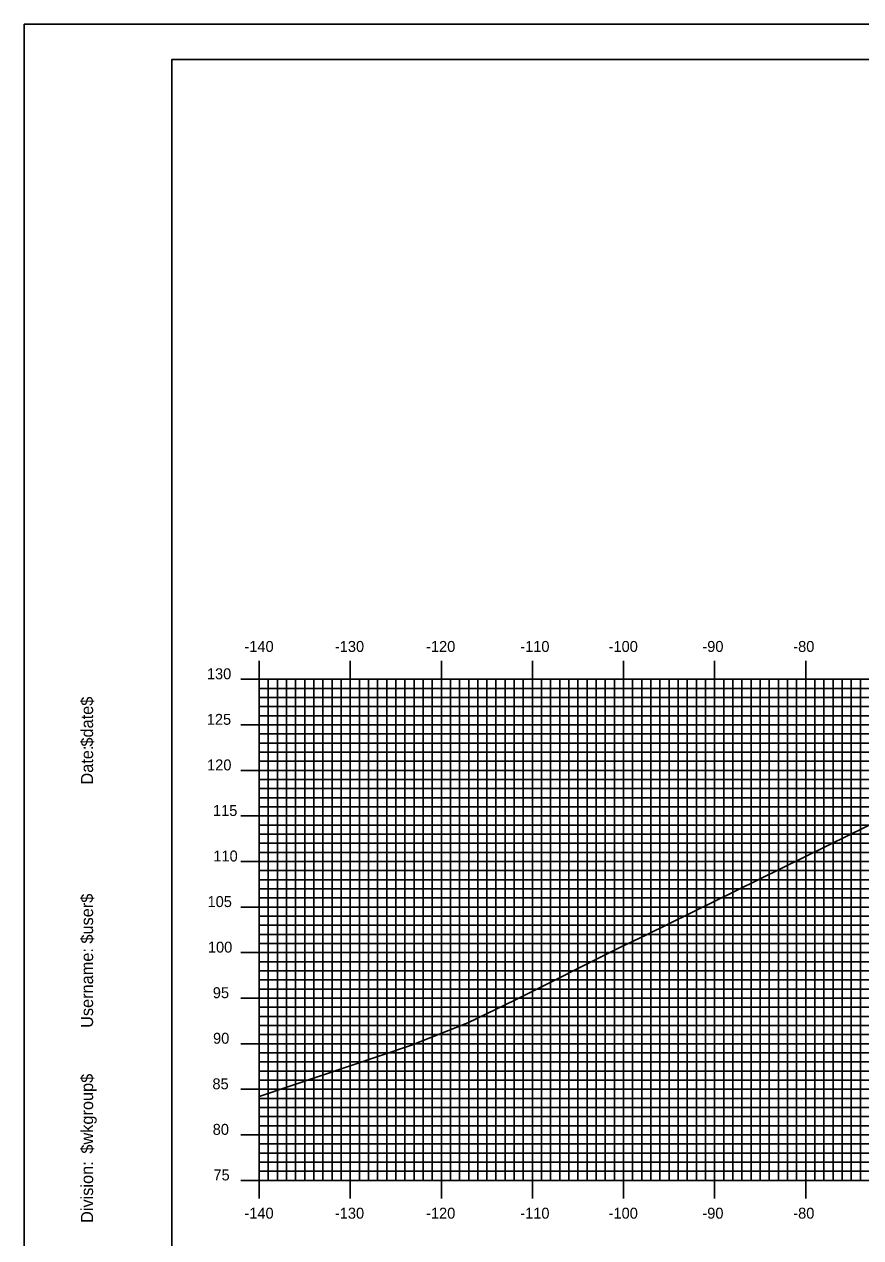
# Model space of a CAD drawing. Extents: x 1684012 to 1684355, y 461260 to 461480.
# Drawn here: x 1684011.9 to 1684103.7, y 461346.8 to 461480 of the extents above; entities that cross this region are included whole.
import ezdxf

# ---------------------------------------------------------------- set-up
doc = ezdxf.new("R2010")
doc.units = 0
for name, color, linetype in [('BORDER', 7, 'Continuous'), ('H_V ANNOTATION', 7, 'Continuous'), ('MAJOR', 7, 'Continuous'), ('MINOR', 7, 'Continuous'), ('PLOT BOUNDARY', 7, 'Continuous'), ('S_Roadway_Centerline', 7, 'Continuous')]:
    doc.layers.add(name, color=color, linetype=linetype)

msp = doc.modelspace()

# ---------------------------------------------------------------- linework, layer by layer
at = {"layer": 'BORDER'}
msp.add_lwpolyline([(1684028.09, 461266.07), (1684348.09, 461266.07), (1684348.09, 461476.07), (1684028.09, 461476.07)], close=True, dxfattribs=at)
at = {"layer": 'MAJOR'}
for p, q in [((1684037.69, 461410.08), (1684037.69, 461408.07)), ((1684047.69, 461410.08), (1684047.69, 461408.07)), ((1684057.69, 461410.08), (1684057.69, 461408.07)), ((1684067.69, 461410.08), (1684067.69, 461408.07)), ((1684077.69, 461410.08), (1684077.69, 461408.07)), ((1684087.69, 461410.08), (1684087.69, 461408.07)), ((1684097.69, 461410.08), (1684097.69, 461408.07)), ((1684035.69, 461408.07), (1684037.69, 461408.07)), ((1684037.69, 461408.07), (1684317.69, 461408.07)), ((1684037.69, 461353.07), (1684037.69, 461408.07)), ((1684037.69, 461353.07), (1684037.69, 461408.07)), ((1684037.69, 461408.07), (1684317.69, 461408.07)), ((1684047.69, 461353.07), (1684047.69, 461408.07)), ((1684057.69, 461353.07), (1684057.69, 461408.07)), ((1684067.69, 461353.07), (1684067.69, 461408.07)), ((1684077.69, 461353.07), (1684077.69, 461408.07)), ((1684087.69, 461353.07), (1684087.69, 461408.07)), ((1684097.69, 461353.07), (1684097.69, 461408.07)), ((1684035.69, 461403.07), (1684037.69, 461403.07)), ((1684037.69, 461403.07), (1684317.69, 461403.07)), ((1684035.69, 461398.07), (1684037.69, 461398.07)), ((1684037.69, 461398.07), (1684317.69, 461398.07)), ((1684035.69, 461393.07), (1684037.69, 461393.07)), ((1684037.69, 461393.07), (1684317.69, 461393.07)), ((1684035.69, 461388.07), (1684037.69, 461388.07)), ((1684037.69, 461388.07), (1684317.69, 461388.07)), ((1684035.69, 461383.07), (1684037.69, 461383.07)), ((1684037.69, 461383.07), (1684317.69, 461383.07)), ((1684035.69, 461378.07), (1684037.69, 461378.07)), ((1684037.69, 461378.07), (1684317.69, 461378.07)), ((1684035.69, 461373.07), (1684037.69, 461373.07)), ((1684037.69, 461373.07), (1684317.69, 461373.07)), ((1684035.69, 461368.07), (1684037.69, 461368.07)), ((1684037.69, 461368.07), (1684317.69, 461368.07)), ((1684035.69, 461363.07), (1684037.69, 461363.07)), ((1684037.69, 461363.07), (1684317.69, 461363.07)), ((1684035.69, 461358.07), (1684037.69, 461358.07)), ((1684037.69, 461358.07), (1684317.69, 461358.07)), ((1684035.69, 461353.07), (1684037.69, 461353.07)), ((1684037.69, 461353.07), (1684317.69, 461353.07)), ((1684037.69, 461353.07), (1684317.69, 461353.07)), ((1684037.69, 461351.07), (1684037.69, 461353.07)), ((1684047.69, 461351.07), (1684047.69, 461353.07)), ((1684057.69, 461351.07), (1684057.69, 461353.07)), ((1684067.69, 461351.07), (1684067.69, 461353.07)), ((1684077.69, 461351.07), (1684077.69, 461353.07)), ((1684087.69, 461351.07), (1684087.69, 461353.07)), ((1684097.69, 461351.07), (1684097.69, 461353.07))]:
    msp.add_line(p, q, dxfattribs=at)
at = {"layer": 'MINOR'}
for p, q in [((1684038.69, 461353.07), (1684038.69, 461408.07)), ((1684039.69, 461353.07), (1684039.69, 461408.07)), ((1684040.69, 461353.07), (1684040.69, 461408.07)), ((1684041.69, 461353.07), (1684041.69, 461408.07)), ((1684042.69, 461353.07), (1684042.69, 461408.07)), ((1684043.69, 461353.07), (1684043.69, 461408.07)), ((1684044.69, 461353.07), (1684044.69, 461408.07)), ((1684045.69, 461353.07), (1684045.69, 461408.07)), ((1684046.69, 461353.07), (1684046.69, 461408.07)), ((1684048.69, 461353.07), (1684048.69, 461408.07)), ((1684049.69, 461353.07), (1684049.69, 461408.07)), ((1684050.69, 461353.07), (1684050.69, 461408.07)), ((1684051.69, 461353.07), (1684051.69, 461408.07)), ((1684052.69, 461353.07), (1684052.69, 461408.07)), ((1684053.69, 461353.07), (1684053.69, 461408.07)), ((1684054.69, 461353.07), (1684054.69, 461408.07)), ((1684055.69, 461353.07), (1684055.69, 461408.07)), ((1684056.69, 461353.07), (1684056.69, 461408.07)), ((1684058.69, 461353.07), (1684058.69, 461408.07)), ((1684059.69, 461353.07), (1684059.69, 461408.07)), ((1684060.69, 461353.07), (1684060.69, 461408.07)), ((1684061.69, 461353.07), (1684061.69, 461408.07)), ((1684062.69, 461353.07), (1684062.69, 461408.07)), ((1684063.69, 461353.07), (1684063.69, 461408.07)), ((1684064.69, 461353.07), (1684064.69, 461408.07)), ((1684065.69, 461353.07), (1684065.69, 461408.07)), ((1684066.69, 461353.07), (1684066.69, 461408.07)), ((1684068.69, 461353.07), (1684068.69, 461408.07)), ((1684069.69, 461353.07), (1684069.69, 461408.07)), ((1684070.69, 461353.07), (1684070.69, 461408.07)), ((1684071.69, 461353.07), (1684071.69, 461408.07)), ((1684072.69, 461353.07), (1684072.69, 461408.07)), ((1684073.69, 461353.07), (1684073.69, 461408.07)), ((1684074.69, 461353.07), (1684074.69, 461408.07)), ((1684075.69, 461353.07), (1684075.69, 461408.07)), ((1684076.69, 461353.07), (1684076.69, 461408.07)), ((1684078.69, 461353.07), (1684078.69, 461408.07)), ((1684079.69, 461353.07), (1684079.69, 461408.07)), ((1684080.69, 461353.07), (1684080.69, 461408.07)), ((1684081.69, 461353.07), (1684081.69, 461408.07)), ((1684082.69, 461353.07), (1684082.69, 461408.07)), ((1684083.69, 461353.07), (1684083.69, 461408.07)), ((1684084.69, 461353.07), (1684084.69, 461408.07)), ((1684085.69, 461353.07), (1684085.69, 461408.07)), ((1684086.69, 461353.07), (1684086.69, 461408.07)), ((1684088.69, 461353.07), (1684088.69, 461408.07)), ((1684089.69, 461353.07), (1684089.69, 461408.07)), ((1684090.69, 461353.07), (1684090.69, 461408.07)), ((1684091.69, 461353.07), (1684091.69, 461408.07)), ((1684092.69, 461353.07), (1684092.69, 461408.07)), ((1684093.69, 461353.07), (1684093.69, 461408.07)), ((1684094.69, 461353.07), (1684094.69, 461408.07)), ((1684095.69, 461353.07), (1684095.69, 461408.07)), ((1684096.69, 461353.07), (1684096.69, 461408.07)), ((1684098.69, 461353.07), (1684098.69, 461408.07)), ((1684099.69, 461353.07), (1684099.69, 461408.07)), ((1684100.69, 461353.07), (1684100.69, 461408.07)), ((1684101.69, 461353.07), (1684101.69, 461408.07)), ((1684102.69, 461353.07), (1684102.69, 461408.07)), ((1684103.69, 461353.07), (1684103.69, 461408.07)), ((1684037.69, 461407.07), (1684317.69, 461407.07)), ((1684037.69, 461407.07), (1684039.69, 461407.07)), ((1684037.69, 461406.07), (1684317.69, 461406.07)), ((1684037.69, 461406.07), (1684039.69, 461406.07)), ((1684037.69, 461405.07), (1684317.69, 461405.07)), ((1684037.69, 461405.07), (1684039.69, 461405.07)), ((1684037.69, 461404.07), (1684317.69, 461404.07)), ((1684037.69, 461404.07), (1684039.69, 461404.07)), ((1684037.69, 461402.07), (1684317.69, 461402.07)), ((1684037.69, 461402.07), (1684039.69, 461402.07)), ((1684037.69, 461401.07), (1684317.69, 461401.07)), ((1684037.69, 461401.07), (1684039.69, 461401.07)), ((1684037.69, 461400.07), (1684317.69, 461400.07)), ((1684037.69, 461400.07), (1684039.69, 461400.07)), ((1684037.69, 461399.07), (1684317.69, 461399.07)), ((1684037.69, 461399.07), (1684039.69, 461399.07)), ((1684037.69, 461397.07), (1684317.69, 461397.07)), ((1684037.69, 461397.07), (1684039.69, 461397.07)), ((1684037.69, 461396.07), (1684317.69, 461396.07)), ((1684037.69, 461396.07), (1684039.69, 461396.07)), ((1684037.69, 461395.07), (1684317.69, 461395.07)), ((1684037.69, 461395.07), (1684039.69, 461395.07)), ((1684037.69, 461394.07), (1684317.69, 461394.07)), ((1684037.69, 461394.07), (1684039.69, 461394.07)), ((1684037.69, 461392.07), (1684317.69, 461392.07)), ((1684037.69, 461392.07), (1684039.69, 461392.07)), ((1684037.69, 461391.07), (1684317.69, 461391.07)), ((1684037.69, 461391.07), (1684039.69, 461391.07)), ((1684037.69, 461390.07), (1684317.69, 461390.07)), ((1684037.69, 461390.07), (1684039.69, 461390.07)), ((1684037.69, 461389.07), (1684317.69, 461389.07)), ((1684037.69, 461389.07), (1684039.69, 461389.07)), ((1684037.69, 461387.07), (1684317.69, 461387.07)), ((1684037.69, 461387.07), (1684039.69, 461387.07)), ((1684037.69, 461386.07), (1684317.69, 461386.07)), ((1684037.69, 461386.07), (1684039.69, 461386.07)), ((1684037.69, 461385.07), (1684317.69, 461385.07)), ((1684037.69, 461385.07), (1684039.69, 461385.07)), ((1684037.69, 461384.07), (1684317.69, 461384.07)), ((1684037.69, 461384.07), (1684039.69, 461384.07)), ((1684037.69, 461382.07), (1684317.69, 461382.07)), ((1684037.69, 461382.07), (1684039.69, 461382.07)), ((1684037.69, 461381.07), (1684317.69, 461381.07)), ((1684037.69, 461381.07), (1684039.69, 461381.07)), ((1684037.69, 461380.07), (1684317.69, 461380.07)), ((1684037.69, 461380.07), (1684039.69, 461380.07)), ((1684037.69, 461379.07), (1684317.69, 461379.07)), ((1684037.69, 461379.07), (1684039.69, 461379.07)), ((1684037.69, 461377.07), (1684317.69, 461377.07)), ((1684037.69, 461377.07), (1684039.69, 461377.07)), ((1684037.69, 461376.07), (1684317.69, 461376.07)), ((1684037.69, 461376.07), (1684039.69, 461376.07)), ((1684037.69, 461375.07), (1684317.69, 461375.07)), ((1684037.69, 461375.07), (1684039.69, 461375.07)), ((1684037.69, 461374.07), (1684317.69, 461374.07)), ((1684037.69, 461374.07), (1684039.69, 461374.07)), ((1684037.69, 461372.07), (1684317.69, 461372.07)), ((1684037.69, 461372.07), (1684039.69, 461372.07)), ((1684037.69, 461371.07), (1684317.69, 461371.07)), ((1684037.69, 461371.07), (1684039.69, 461371.07)), ((1684037.69, 461370.07), (1684317.69, 461370.07)), ((1684037.69, 461370.07), (1684039.69, 461370.07)), ((1684037.69, 461369.07), (1684317.69, 461369.07)), ((1684037.69, 461369.07), (1684039.69, 461369.07)), ((1684037.69, 461367.07), (1684317.69, 461367.07)), ((1684037.69, 461367.07), (1684039.69, 461367.07)), ((1684037.69, 461366.07), (1684317.69, 461366.07)), ((1684037.69, 461366.07), (1684039.69, 461366.07)), ((1684037.69, 461365.07), (1684317.69, 461365.07)), ((1684037.69, 461365.07), (1684039.69, 461365.07)), ((1684037.69, 461364.07), (1684317.69, 461364.07)), ((1684037.69, 461364.07), (1684039.69, 461364.07)), ((1684037.69, 461362.07), (1684317.69, 461362.07)), ((1684037.69, 461362.07), (1684039.69, 461362.07)), ((1684037.69, 461361.07), (1684317.69, 461361.07)), ((1684037.69, 461361.07), (1684039.69, 461361.07)), ((1684037.69, 461360.07), (1684317.69, 461360.07)), ((1684037.69, 461360.07), (1684039.69, 461360.07)), ((1684037.69, 461359.07), (1684317.69, 461359.07)), ((1684037.69, 461359.07), (1684039.69, 461359.07)), ((1684037.69, 461357.07), (1684317.69, 461357.07)), ((1684037.69, 461357.07), (1684039.69, 461357.07)), ((1684037.69, 461356.07), (1684317.69, 461356.07)), ((1684037.69, 461356.07), (1684039.69, 461356.07)), ((1684037.69, 461355.07), (1684317.69, 461355.07)), ((1684037.69, 461355.07), (1684039.69, 461355.07)), ((1684037.69, 461354.07), (1684317.69, 461354.07)), ((1684037.69, 461354.07), (1684039.69, 461354.07))]:
    msp.add_line(p, q, dxfattribs=at)
at = {"layer": 'PLOT BOUNDARY'}
msp.add_lwpolyline([(1684011.9, 461259.95), (1684351.9, 461259.95), (1684351.9, 461479.95), (1684011.9, 461479.95)], close=True, dxfattribs=at)
at = {"layer": 'S_Roadway_Centerline'}
msp.add_lwpolyline([(1684037.69, 461362.29), (1684054.4, 461367.92), (1684060.59, 461370.38), (1684065.75, 461372.84), (1684077.37, 461378.68), (1684080.2, 461380.03), (1684102.5, 461391), (1684109.72, 461394.52)], dxfattribs=at)

# ---------------------------------------------------------------- texts
at = {"layer": 'BORDER'}
for s, p in [('$date$', (1684019.46, 461400.68)), ('Date:', (1684019.46, 461396.51)), ('$user$', (1684019.46, 461379.06)), ('Username:', (1684019.46, 461369.81)), ('$wkgroup$', (1684019.46, 461356.01)), ('Division:', (1684019.46, 461348.4))]:
    msp.add_text(s, height=1.339, rotation=90, dxfattribs=at).set_placement(p)
at = {"layer": 'H_V ANNOTATION'}
for s, p in [('-140', (1684036.07, 461411.07)), ('-130', (1684046, 461411.07)), ('-120', (1684056.01, 461411.07)), ('-110', (1684066.35, 461411.07)), ('-100', (1684076.05, 461411.07)), ('-90', (1684086.34, 461411.07)), ('-80', (1684096.32, 461411.07)), ('130', (1684031.95, 461408.07)), ('125', (1684031.94, 461403.07)), ('120', (1684031.97, 461398.07)), ('115', (1684032.62, 461393.07)), ('110', (1684032.66, 461388.07)), ('105', (1684032.02, 461383.07)), ('100', (1684032.06, 461378.07)), ('95', (1684032.6, 461373.07)), ('90', (1684032.63, 461368.07)), ('85', (1684032.56, 461363.07)), ('80', (1684032.59, 461358.07)), ('75', (1684032.67, 461353.07)), ('-140', (1684036.07, 461348.87)), ('-130', (1684046, 461348.87)), ('-120', (1684056.01, 461348.87)), ('-110', (1684066.35, 461348.87)), ('-100', (1684076.05, 461348.87)), ('-90', (1684086.34, 461348.87)), ('-80', (1684096.32, 461348.87))]:
    msp.add_text(s, height=1.2, dxfattribs=at).set_placement(p)
at = {"layer": 'MAJOR'}
msp.add_text('-', height=0.012, dxfattribs=at).set_placement((1684037.68, 461353.07))

doc.saveas('drawing.dxf')
